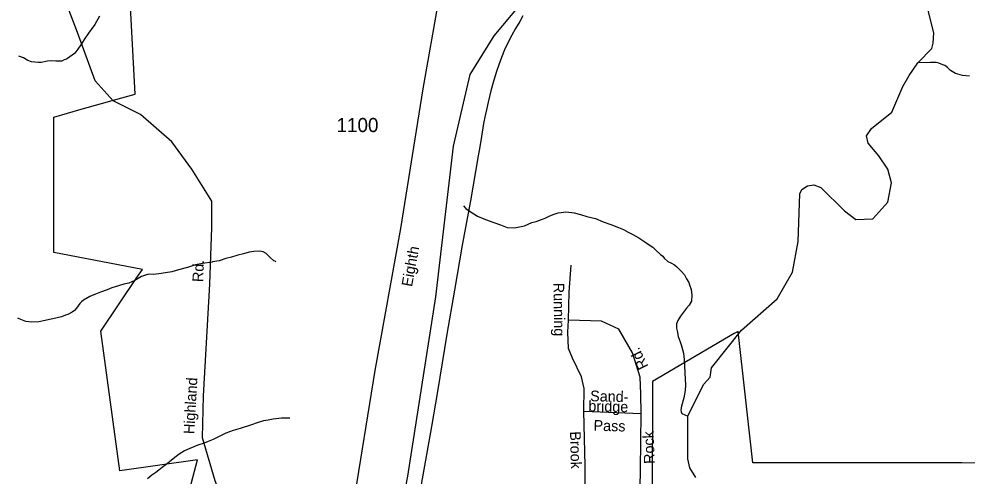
# Model space of a CAD drawing. Extents: x 2056842 to 2160602, y 826753 to 1016856.
# Drawn here: x 2061647 to 2070045, y 856821 to 860868 of the extents above; entities that cross this region are included whole.
import ezdxf

# ---------------------------------------------------------------- set-up
doc = ezdxf.new("R2010")
doc.units = 0
for name, color, linetype in [('Exist Boundary Land Use Reservation Military US Department of Defense', 7, 'Continuous'), ('Exist Boundary Political City Limit New', 7, 'Continuous'), ('Exist Hydrographic Creek Single Shore', 7, 'Continuous'), ('Exist Railroad Mainline', 7, 'Continuous'), ('Exist Road Non-System Type 51', 7, 'Continuous'), ('Exist Road Non-System Type 51 Label', 7, 'Continuous'), ('Exist Road Secondary Type 51 Attributed', 7, 'Continuous'), ('Exist Road Secondary Type 51 Label', 7, 'Continuous'), ('Exist Road Secondary Type 51 Number Label', 7, 'Continuous'), ('Map Preparation Boundary City Limit Buffer Line', 7, 'Continuous')]:
    doc.layers.add(name, color=color, linetype=linetype)

msp = doc.modelspace()

# ---------------------------------------------------------------- linework, layer by layer
at = {"layer": 'Exist Boundary Land Use Reservation Military US Department of Defense'}
msp.add_lwpolyline([(2066174.9, 861104.2), (2065853.1, 860720.1), (2065640.8, 860375.6), (2065493.3, 859741.1), (2065336, 858409.3), (2065087.8, 856821.5), (2065002.7, 856377.5), (2064755.9, 854722.1), (2064712.1, 854064.9), (2064745.7, 853597), (2064847.7, 853049), (2064892.2, 852688.1), (2064867, 852393.5), (2064779.9, 852040.8), (2064686.1, 851837.6), (2064419.3, 851474.7), (2064046, 851187.2), (2063767.2, 850891.2), (2063676.8, 850746.1), (2063576.4, 850501.5), (2063457.1, 850039.1), (2063355.1, 849757.2), (2063118.8, 849274.6)], dxfattribs=at)
at = {"layer": 'Exist Boundary Political City Limit New'}
for points in [[(2062783.2, 855275.6), (2063229.1, 856963.7), (2062540.8, 856868.5), (2062371.8, 858105.4), (2062692.5, 858577.8), (2062740.8, 858648.8), (2062663.9, 858663.6), (2061954.5, 858800.4), (2061956.2, 860000), (2062196.6, 860069), (2062378.1, 860121.1), (2062471.4, 860147.8), (2062676.2, 860203.4), (2062618.2, 861309.8)], [(2069999.4, 856937.9), (2068148.5, 856937.9), (2068017.8, 858102.1), (2067982.8, 858081.9), (2067259.8, 857659.2), (2067253, 855485.2)], [(2070806.6, 856932.3), (2070000, 856937.9), (2069999.4, 856937.9)]]:
    msp.add_lwpolyline(points, dxfattribs=at)
at = {"layer": 'Exist Hydrographic Creek Single Shore'}
for points in [[(2067643.2, 856807.6), (2067589.5, 856893.4), (2067572.8, 856974.1), (2067571.6, 857352.3), (2067711, 857630.7), (2067769.8, 857696), (2067780.1, 857779.2), (2068046.2, 858113.9), (2068363.7, 858389.8), (2068498, 858626.6), (2068547.9, 858899.2), (2068564.5, 859319.7), (2068582.4, 859358.1), (2068631, 859391.4), (2068688.6, 859400.4), (2068749.8, 859376.1), (2068958.5, 859170), (2069060.4, 859092.3), (2069211.6, 859098.3), (2069342.1, 859245.5), (2069375.3, 859417.7), (2069343.3, 859538), (2069264, 859655.1), (2069168.1, 859769), (2069152.7, 859833), (2069198.8, 859898.3), (2069378.7, 860042.3), (2069475.9, 860271.5), (2069533.4, 860368.9), (2069607.6, 860479.5), (2069731.7, 860608.1), (2069744.5, 860652.9), (2069750.9, 860746.4), (2069619.2, 861261.6)], [(2062361.4, 860892.5), (2062319.7, 860820.5), (2062287.7, 860776.2), (2062261.9, 860742), (2062230.1, 860696.1), (2062194, 860639.9), (2062168.2, 860602.1), (2062142.2, 860566.2), (2062138.1, 860562), (2062078, 860517.9), (2062068.1, 860511.7), (2062048.5, 860505.8), (2062026.3, 860495.7), (2061972.4, 860493.8), (2061938.3, 860497.8), (2061898.4, 860495.6), (2061842.6, 860481.4), (2061816.1, 860481.4), (2061786.2, 860485.5), (2061758.3, 860489.3), (2061726.3, 860501.1), (2061686.1, 860523), (2061645.9, 860539.2)], [(2070067.6, 860360.7), (2070005.7, 860368.5), (2069941.5, 860384.3), (2069897.8, 860412.4), (2069871.6, 860438.3), (2069847.8, 860456.2), (2069829.6, 860462.1), (2069795.3, 860478.3), (2069771.3, 860482.3), (2069759.4, 860484.2), (2069721.5, 860483.8), (2069607.6, 860479.5)], [(2065584, 859212.4), (2065606.3, 859188.7), (2065642.4, 859162.5), (2065708.4, 859122.9), (2065780.4, 859092.9), (2065852.2, 859064.9), (2065912.7, 859045.2), (2065972.3, 859021.2), (2066036.7, 859019.5), (2066124.3, 859037.5), (2066190.5, 859065.5), (2066228.4, 859073.6), (2066274.4, 859091.8), (2066306.6, 859105.6), (2066344.5, 859121.8), (2066378.1, 859138.1), (2066424.3, 859151.9), (2066450.1, 859154), (2066490.3, 859160.1), (2066544.4, 859154.3), (2066566.2, 859152.2), (2066620.5, 859138.3), (2066676.1, 859120.6), (2066754.4, 859102.6), (2066820.2, 859072.7), (2066888.5, 859049), (2066958.6, 859022.9), (2067000.3, 859005.3), (2067042.5, 858981), (2067084.3, 858959.2), (2067136.8, 858929.3), (2067190.5, 858895.3), (2067230.5, 858869.7), (2067260.9, 858847.6), (2067288.8, 858821.5), (2067328.7, 858783.8), (2067350.9, 858767.9), (2067363, 858751.8), (2067395.2, 858719.8), (2067421.2, 858708.1), (2067454.6, 858690), (2067474.9, 858674), (2067516.8, 858631.9), (2067541.2, 858602.2), (2067561.1, 858568.4), (2067579.1, 858534), (2067587.3, 858514.1), (2067601.7, 858472.2), (2067607.2, 858422.2), (2067603.5, 858368.4), (2067583.6, 858334.1), (2067559.8, 858308.1), (2067525.8, 858260.1), (2067508, 858236.1), (2067484.2, 858197.9), (2067470.2, 858167.9), (2067472.3, 858131.9), (2067476, 858106.2), (2067486.4, 858055.9), (2067504.3, 858008.1), (2067516.6, 857974.2), (2067532.2, 857910.2), (2067538.5, 857854), (2067548.5, 857678.7), (2067549.8, 857630.1), (2067548.5, 857577.6), (2067535.7, 857514.9), (2067516.5, 857440.6), (2067508.9, 857408.6), (2067511.4, 857390.3), (2067519.4, 857374.1), (2067571.6, 857352.3)], [(2063916, 858722.5), (2063923.2, 858719.3), (2063916, 858722.5), (2063905.4, 858727.3), (2063873.4, 858755.2), (2063835.3, 858791.4), (2063811.3, 858805.2), (2063779.5, 858813.3), (2063727.4, 858809), (2063685, 858804.9), (2063637.2, 858789), (2063585.1, 858777), (2063529.3, 858758.7), (2063479.5, 858746.8), (2063419.6, 858726.7), (2063361.4, 858716.4), (2063357.5, 858716.2), (2063271.4, 858704.1), (2063211.5, 858690), (2063139.5, 858668.2), (2063059.8, 858645.8), (2063001.3, 858629.9), (2062905.6, 858615.6), (2062841.8, 858605.4), (2062795.9, 858607.5), (2062767.6, 858601.2), (2062733.7, 858587.3), (2062673.7, 858553), (2062619.9, 858529), (2062575.8, 858519.1), (2062528.1, 858504.8), (2062470.2, 858486.8), (2062428, 858470.5), (2062370, 858448.5), (2062326.1, 858430.4), (2062273.8, 858410.3), (2062218, 858378.2), (2062200.4, 858364.3), (2062186.2, 858348.2), (2062156.1, 858308.1), (2062138.5, 858286), (2062118.2, 858272), (2062080.4, 858252.2), (2062058.3, 858244.2), (2062022.4, 858232.2), (2061984.5, 858221.7), (2061948.4, 858213.8), (2061918.4, 858205.8), (2061878.5, 858197.6), (2061822.9, 858187.4), (2061760.6, 858183.5), (2061734.5, 858185.4), (2061708.9, 858189.3), (2061664.2, 858207.4), (2061636.5, 858219.3)], [(2064045.9, 857333.7), (2064008.1, 857333.7), (2063971.8, 857333.5), (2063898, 857325.7), (2063854.1, 857317.3), (2063813.9, 857309.2), (2063755.7, 857291.2), (2063707.7, 857273.3), (2063605.8, 857240.9), (2063544.1, 857224.7), (2063478.1, 857200.7), (2063444, 857182.7), (2063408.4, 857164.6), (2063366.3, 857144.6), (2063324.3, 857126.6), (2063288.4, 857112.6), (2063230.4, 857094.2), (2063160.4, 857066.3), (2063114.5, 857044), (2063066.7, 857014), (2063012.8, 856973.8), (2062963, 856931.9), (2062916.8, 856897.9), (2062886.9, 856873.6), (2062858.8, 856853.6), (2062825.2, 856829.5), (2062787, 856797.5)]]:
    msp.add_lwpolyline(points, dxfattribs=at)
at = {"layer": 'Exist Railroad Mainline'}
msp.add_lwpolyline([(2066111.5, 860895.2), (2066082.5, 860845.8), (2066045.2, 860784.6), (2066012, 860725.3), (2065982.8, 860667.8), (2065947.3, 860594.6), (2065919.9, 860527.1), (2065898.5, 860461.6), (2065877.3, 860402), (2065853.7, 860326.5), (2065827.8, 860233), (2065803.7, 860131.5), (2065788.3, 860063.8), (2065777.3, 860014), (2065761.8, 859942.3), (2065743.4, 859826.7), (2065729.6, 859736.9), (2065715.9, 859657.2), (2065645.7, 859256.6), (2065573.6, 858864), (2065503.4, 858467.4), (2065437.4, 858078.8), (2065352.9, 857568.4), (2065300.5, 857259.5), (2065209.9, 856745.3)], dxfattribs=at)
at = {"layer": 'Exist Road Non-System Type 51'}
msp.add_line((2066651.7, 857396.9), (2067158.5, 857376.1), dxfattribs=at)
for points in [[(2064026.4, 856174.8), (2063635.4, 856405.6), (2063477.2, 856535.9), (2063384.1, 856778.1), (2063272.4, 857159.9), (2063281.7, 857532.4), (2063337.6, 858519.6), (2063356.2, 859022.5), (2063356.2, 859255.3), (2063179.4, 859538.4), (2063002.5, 859780.6), (2062723.3, 860022.7), (2062481.4, 860143.8), (2062323.2, 860320.7), (2062164.9, 860749.1), (2061988.1, 861214.8)], [(2066515.6, 858200.2), (2066520.8, 858450.7), (2066539.5, 858687.6)], [(2066651.7, 857396.9), (2066654.8, 857597.5), (2066629.9, 857699.3), (2066550.9, 857865.6), (2066513.6, 857950.8), (2066509.4, 858094.2), (2066515.6, 858200.2)], [(2067158.5, 857376.1), (2067155.3, 857547.6), (2067149.1, 857697.3), (2067080.6, 857913.4), (2066960.1, 858121.3), (2066806.4, 858191.9), (2066611.2, 858198.2), (2066515.6, 858200.2)], [(2066676.6, 856397.2), (2066661, 856568.7), (2066663.1, 856911.6), (2066651.7, 857396.9)], [(2067142.9, 856394.1), (2067153.3, 856878.4), (2067158.5, 857376.1)]]:
    msp.add_lwpolyline(points, dxfattribs=at)
at = {"layer": 'Exist Road Secondary Type 51 Attributed'}
msp.add_lwpolyline([(2064684.1, 855839.6), (2064643.1, 855944), (2064589.1, 856124.9), (2064578.7, 856311.9), (2064608.8, 856568.6), (2064801, 857754.3), (2065030.5, 859012.8), (2065226.7, 860248.4), (2065364.9, 861035.1), (2065425.1, 861317.8), (2065553.9, 861629.5), (2065725.2, 861986), (2065930.8, 862276.9), (2066130.2, 862526.4), (2066317.1, 862696.8), (2066825, 863107.3), (2067775.2, 863846.1), (2068132.4, 864147.5), (2068556.1, 864440.6), (2069020.3, 864778.3), (2069626.8, 865266.7), (2069800.3, 865437.4)], dxfattribs=at)
at = {"layer": 'Map Preparation Boundary City Limit Buffer Line'}
for points in [[(2062783.2, 855275.6), (2063229.1, 856963.7), (2062540.8, 856868.5), (2062371.8, 858105.4), (2062692.5, 858577.8), (2062740.8, 858648.8), (2062663.9, 858663.6), (2061954.5, 858800.4), (2061956.2, 860000), (2062196.6, 860069), (2062378.1, 860121.1), (2062471.4, 860147.8), (2062676.2, 860203.4), (2062618.2, 861309.8)], [(2069999.4, 856937.9), (2068148.5, 856937.9), (2068017.8, 858102.1), (2067982.8, 858081.9), (2067259.8, 857659.2), (2067253, 855485.2)], [(2070806.6, 856932.3), (2070000, 856937.9), (2069999.4, 856937.9)]]:
    msp.add_lwpolyline(points, dxfattribs=at)

# ---------------------------------------------------------------- texts
at = {"layer": 'Exist Road Non-System Type 51 Label'}
for s, rotation, p in [('Rd.', 87.87737, (2063278.1, 858537.3)), ('Running', 270.85865, (2066381, 858531.9)), ('Rd.', 116.64988, (2067224.8, 857793.2)), ('Highland', 86.83873, (2063200.1, 857190.6)), ('Sand-', 358.5996, (2066705.8, 857483.7)), ('bridge', 358.5996, (2066689.7, 857394.7)), ('Pass', 358.5996, (2066735.6, 857222.3)), ('Brook', 271.38293, (2066527.8, 857216.1)), ('Rock', 92.25983, (2067279.2, 856930.6))]:
    msp.add_text(s, height=95, rotation=rotation, dxfattribs=at).set_placement(p)
at = {"layer": 'Exist Road Secondary Type 51 Label'}
msp.add_text('Eighth', height=95, rotation=79.52222, dxfattribs=at).set_placement((2065128.1, 858492.7))
at = {"layer": 'Exist Road Secondary Type 51 Number Label'}
msp.add_text('1100', height=125, dxfattribs=at).set_placement((2064459.5, 859866.8))

doc.saveas('drawing.dxf')
